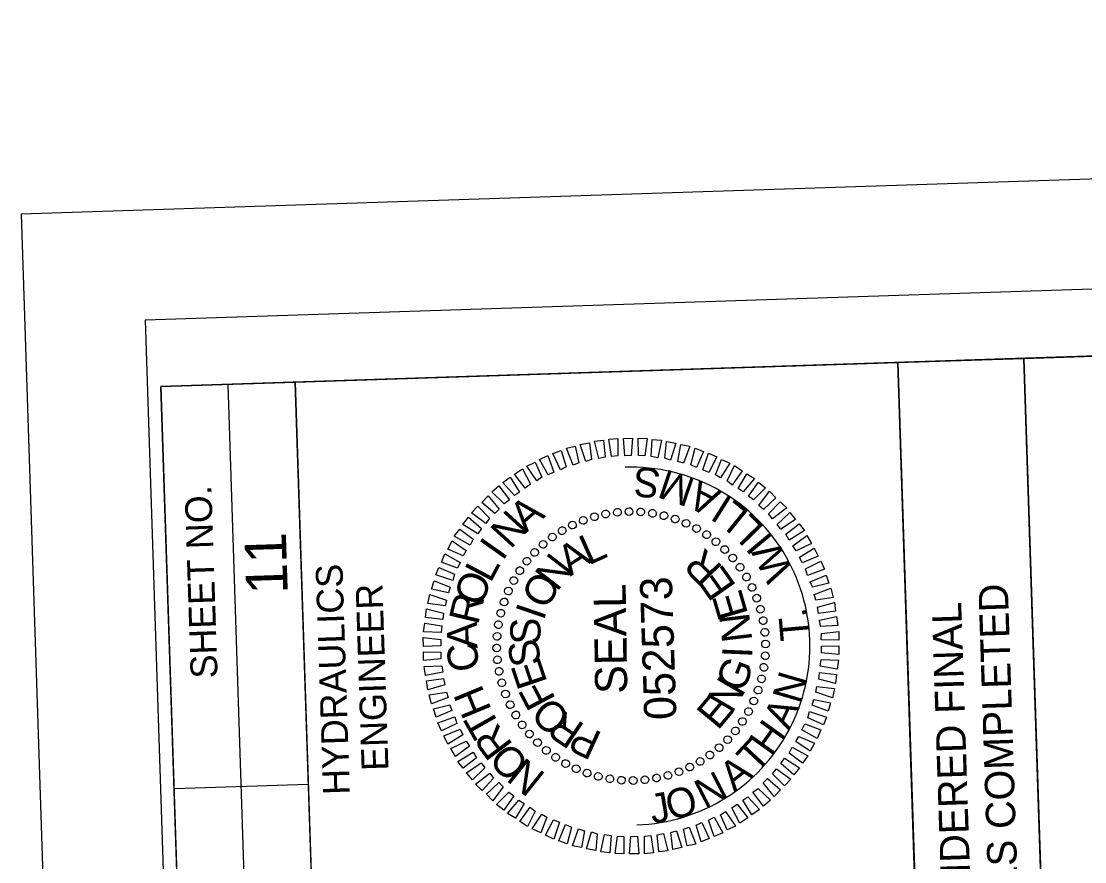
# Model space of a CAD drawing. Extents: x 1627314 to 1628469, y 762309 to 764253.
# Drawn here: x 1627314.2 to 1627512.6, y 763887.6 to 764044.4 of the extents above; entities that cross this region are included whole.
import ezdxf

# ---------------------------------------------------------------- set-up
doc = ezdxf.new("R2010")
doc.units = 0
for name, color, linetype in [('Old_Level_58', 7, 'Continuous'), ('Scratch_Level_0', 7, 'Continuous'), ('Sheet Data Field CELL', 7, 'Continuous'), ('Sheet Plot Border Inside CELL', 7, 'Continuous'), ('Sheet Plot Border Outside CELL', 7, 'Continuous'), ('Sheet Professional Seal CELL', 7, 'Continuous'), ('Sheet Profile CELL', 7, 'Continuous'), ('Sheet Profile Grid Major CELL', 7, 'Continuous'), ('Sheet Profile Grid Minor CELL', 7, 'Continuous'), ('Sheet Sticker Exception Certification CELL', 7, 'Continuous')]:
    doc.layers.add(name, color=color, linetype=linetype)

msp = doc.modelspace()

# ---------------------------------------------------------------- linework, layer by layer
at = {"layer": 'Old_Level_58'}
msp.add_lwpolyline([(1627507.79, 763781.61), (1627501.25, 763981.49), (1627565.16, 763983.58), (1627571.7, 763783.7)], close=True, dxfattribs=at)
at = {"layer": 'Scratch_Level_0'}
msp.add_arc((1627428, 763927.84), 33.36, 271.8735, 91.8735, dxfattribs=at)
at = {"layer": 'Sheet Plot Border Inside CELL'}
msp.add_lwpolyline([(1628446.34, 762357.53), (1628391.86, 764023.14), (1627337.33, 763988.65), (1627391.81, 762323.04)], close=True, dxfattribs=at)
at = {"layer": 'Sheet Plot Border Outside CELL'}
msp.add_lwpolyline([(1628469.21, 762345.27), (1628413.63, 764044.37), (1627314.22, 764008.4), (1627369.79, 762309.31)], close=True, dxfattribs=at)
at = {"layer": 'Sheet Professional Seal CELL'}
for p, q in [((1627421.1, 763951.98), (1627421.1, 763951.98)), ((1627423.29, 763952.45), (1627423.29, 763952.45)), ((1627425.43, 763952.82), (1627425.43, 763952.82)), ((1627427.62, 763952.94), (1627427.62, 763952.94)), ((1627429.83, 763952.86), (1627429.83, 763952.86)), ((1627431.99, 763952.58), (1627431.99, 763952.58)), ((1627434.1, 763952.2), (1627434.1, 763952.2)), ((1627436.22, 763951.57), (1627436.22, 763951.57)), ((1627417.05, 763950.44), (1627417.05, 763950.44)), ((1627419.02, 763951.31), (1627419.02, 763951.31)), ((1627438.25, 763950.74), (1627438.25, 763950.74)), ((1627440.23, 763949.8), (1627440.23, 763949.8)), ((1627413.27, 763948.17), (1627413.27, 763948.17)), ((1627415.13, 763949.38), (1627415.13, 763949.38)), ((1627442.07, 763948.61), (1627442.07, 763948.61)), ((1627411.56, 763946.86), (1627411.56, 763946.86)), ((1627443.87, 763947.32), (1627443.87, 763947.32)), ((1627445.47, 763945.87), (1627445.47, 763945.87)), ((1627408.52, 763943.71), (1627408.52, 763943.71)), ((1627409.96, 763945.31), (1627409.96, 763945.31)), ((1627447.02, 763944.27), (1627447.02, 763944.27)), ((1627407.22, 763941.92), (1627407.22, 763941.92)), ((1627448.33, 763942.56), (1627448.33, 763942.56)), ((1627406.03, 763940.08), (1627406.03, 763940.08)), ((1627449.54, 763940.7), (1627449.54, 763940.7)), ((1627405.1, 763938.1), (1627405.1, 763938.1)), ((1627450.6, 763938.78), (1627450.6, 763938.78)), ((1627404.26, 763936.07), (1627404.26, 763936.07)), ((1627451.46, 763936.81), (1627451.46, 763936.81)), ((1627403.63, 763933.95), (1627403.63, 763933.95)), ((1627452.13, 763934.73), (1627452.13, 763934.73)), ((1627403.25, 763931.83), (1627403.25, 763931.83)), ((1627452.6, 763932.55), (1627452.6, 763932.55)), ((1627402.97, 763929.67), (1627402.97, 763929.67)), ((1627452.98, 763930.41), (1627452.98, 763930.41)), ((1627428, 763927.84), (1627428, 763927.84)), ((1627453.1, 763928.21), (1627453.1, 763928.21)), ((1627402.89, 763927.47), (1627402.89, 763927.47)), ((1627453.02, 763926.01), (1627453.02, 763926.01)), ((1627403.02, 763925.27), (1627403.02, 763925.27)), ((1627452.74, 763923.85), (1627452.74, 763923.85)), ((1627403.39, 763923.13), (1627403.39, 763923.13)), ((1627452.36, 763921.73), (1627452.36, 763921.73)), ((1627403.86, 763920.95), (1627403.86, 763920.95)), ((1627404.53, 763918.87), (1627404.53, 763918.87)), ((1627451.73, 763919.61), (1627451.73, 763919.61)), ((1627405.39, 763916.89), (1627405.39, 763916.89)), ((1627450.89, 763917.58), (1627450.89, 763917.58)), ((1627406.45, 763914.98), (1627406.45, 763914.98)), ((1627448.77, 763913.76), (1627448.77, 763913.76)), ((1627449.96, 763915.6), (1627449.96, 763915.6)), ((1627407.67, 763913.12), (1627407.67, 763913.12)), ((1627447.47, 763911.97), (1627447.47, 763911.97)), ((1627408.97, 763911.41), (1627408.97, 763911.41)), ((1627410.53, 763909.81), (1627410.53, 763909.81)), ((1627446.03, 763910.37), (1627446.03, 763910.37)), ((1627412.12, 763908.36), (1627412.12, 763908.36)), ((1627444.43, 763908.82), (1627444.43, 763908.82)), ((1627413.92, 763907.07), (1627413.92, 763907.07)), ((1627415.76, 763905.88), (1627415.76, 763905.88)), ((1627440.86, 763906.3), (1627440.86, 763906.3)), ((1627442.72, 763907.51), (1627442.72, 763907.51)), ((1627417.74, 763904.94), (1627417.74, 763904.94)), ((1627419.77, 763904.11), (1627419.77, 763904.11)), ((1627436.97, 763904.37), (1627436.97, 763904.37)), ((1627438.94, 763905.23), (1627438.94, 763905.23)), ((1627421.89, 763903.48), (1627421.89, 763903.48)), ((1627424, 763903.09), (1627424, 763903.09)), ((1627426.16, 763902.82), (1627426.16, 763902.82)), ((1627428.37, 763902.74), (1627428.37, 763902.74)), ((1627430.56, 763902.86), (1627430.56, 763902.86)), ((1627432.7, 763903.23), (1627432.7, 763903.23)), ((1627434.89, 763903.7), (1627434.89, 763903.7))]:
    msp.add_line(p, q, dxfattribs=at)
for points in [[(1627419.57, 763962.28), (1627418.51, 763965.4), (1627420.2, 763965.75), (1627420.6, 763962.62)], [(1627421.95, 763962.81), (1627421.14, 763966.03), (1627422.84, 763966.24), (1627423.14, 763963.05)], [(1627424.34, 763963.19), (1627423.83, 763966.42), (1627425.53, 763966.58), (1627425.53, 763963.33)], [(1627426.84, 763963.32), (1627426.58, 763966.56), (1627428.28, 763966.62), (1627428.03, 763963.36)], [(1627429.34, 763963.35), (1627429.33, 763966.6), (1627430.98, 763966.56), (1627430.54, 763963.29)], [(1627431.74, 763963.18), (1627431.94, 763966.39), (1627433.64, 763966.24), (1627432.95, 763962.97)], [(1627434.3, 763962.86), (1627434.6, 763965.97), (1627436.31, 763965.68), (1627435.37, 763962.5)], [(1627436.72, 763962.29), (1627437.27, 763965.41), (1627438.93, 763965.12), (1627437.79, 763961.93)], [(1627412.49, 763959.75), (1627410.9, 763962.65), (1627412.48, 763963.35), (1627413.58, 763960.28)], [(1627414.81, 763960.72), (1627413.41, 763963.73), (1627414.95, 763964.33), (1627415.85, 763961.26)], [(1627417.19, 763961.6), (1627415.93, 763964.76), (1627417.57, 763965.12), (1627418.22, 763961.99)], [(1627439.15, 763961.62), (1627439.95, 763964.75), (1627441.52, 763964.15), (1627440.21, 763961.11)], [(1627441.38, 763960.69), (1627442.43, 763963.83), (1627444, 763963.13), (1627442.49, 763960.23)], [(1627410.38, 763958.68), (1627408.54, 763961.42), (1627410.07, 763962.12), (1627411.31, 763959.31)], [(1627443.71, 763959.77), (1627444.87, 763962.66), (1627446.44, 763961.96), (1627444.68, 763959.2)], [(1627445.9, 763958.64), (1627447.31, 763961.49), (1627448.74, 763960.53), (1627446.82, 763957.87)], [(1627408.22, 763957.31), (1627406.24, 763959.89), (1627407.7, 763960.89), (1627409.2, 763958.04)], [(1627447.95, 763957.21), (1627449.56, 763959.96), (1627451.04, 763959.06), (1627448.92, 763956.59)], [(1627404.32, 763954.38), (1627401.99, 763956.6), (1627403.31, 763957.7), (1627405.29, 763955.11)], [(1627406.22, 763955.94), (1627404.04, 763958.32), (1627405.45, 763959.32), (1627407.15, 763956.57)], [(1627449.89, 763955.77), (1627451.76, 763958.43), (1627453.09, 763957.37), (1627450.82, 763955.1)], [(1627402.57, 763952.57), (1627400.15, 763954.64), (1627401.31, 763955.88), (1627403.35, 763953.35)], [(1627451.85, 763954.08), (1627453.82, 763956.7), (1627455.01, 763955.49), (1627452.68, 763953.31)], [(1627400.88, 763950.71), (1627398.22, 763952.68), (1627399.38, 763953.92), (1627401.6, 763951.69)], [(1627453.65, 763952.49), (1627455.78, 763954.76), (1627457.02, 763953.6), (1627454.38, 763951.56)], [(1627399.4, 763948.76), (1627396.59, 763950.52), (1627397.64, 763951.86), (1627400.06, 763949.74)], [(1627455.27, 763950.54), (1627457.6, 763952.77), (1627458.69, 763951.45), (1627455.95, 763949.61)], [(1627397.96, 763946.67), (1627395.01, 763948.32), (1627396.02, 763949.65), (1627398.53, 763947.79)], [(1627456.83, 763948.69), (1627459.32, 763950.62), (1627460.31, 763949.36), (1627457.46, 763947.61)], [(1627396.68, 763944.67), (1627393.79, 763945.93), (1627394.59, 763947.46), (1627397.25, 763945.64)], [(1627458.15, 763946.53), (1627460.79, 763948.47), (1627461.64, 763946.95), (1627458.78, 763945.6)], [(1627459.42, 763944.42), (1627462.17, 763946.12), (1627462.92, 763944.59), (1627459.91, 763943.34)], [(1627395.6, 763942.34), (1627392.62, 763943.49), (1627393.26, 763945.06), (1627396.12, 763943.45)], [(1627460.54, 763942.26), (1627463.4, 763943.65), (1627464.05, 763942.17), (1627460.88, 763941.02)], [(1627394.73, 763940.06), (1627391.54, 763941.1), (1627392.1, 763942.52), (1627395.04, 763941.22)], [(1627393.9, 763937.78), (1627390.78, 763938.43), (1627391.23, 763939.99), (1627394.22, 763938.84)], [(1627461.42, 763939.84), (1627464.38, 763941.08), (1627464.88, 763939.55), (1627461.81, 763938.8)], [(1627462.15, 763937.46), (1627465.26, 763938.61), (1627465.67, 763936.92), (1627462.43, 763936.42)], [(1627393.33, 763935.36), (1627390.07, 763935.75), (1627390.41, 763937.46), (1627393.55, 763936.42)], [(1627462.78, 763935.08), (1627465.95, 763935.98), (1627466.15, 763934.34), (1627462.97, 763933.88)], [(1627392.86, 763932.79), (1627389.65, 763933.14), (1627389.85, 763934.79), (1627392.98, 763934)], [(1627392.54, 763930.38), (1627389.29, 763930.47), (1627389.53, 763932.13), (1627392.7, 763931.59)], [(1627463.16, 763932.69), (1627466.34, 763933.34), (1627466.59, 763931.65), (1627463.34, 763931.5)], [(1627463.49, 763930.2), (1627466.73, 763930.56), (1627466.73, 763928.91), (1627463.48, 763929)], [(1627392.48, 763927.88), (1627389.23, 763927.77), (1627389.22, 763929.42), (1627392.49, 763929.08)], [(1627463.52, 763927.8), (1627466.76, 763927.91), (1627466.77, 763926.26), (1627463.51, 763926.6)], [(1627392.5, 763925.48), (1627389.26, 763925.12), (1627389.26, 763926.77), (1627392.51, 763926.68)], [(1627392.84, 763922.99), (1627389.66, 763922.33), (1627389.4, 763924.02), (1627392.65, 763924.18)], [(1627463.45, 763925.3), (1627466.7, 763925.2), (1627466.46, 763923.54), (1627463.29, 763924.09)], [(1627393.21, 763920.6), (1627390.04, 763919.69), (1627389.84, 763921.34), (1627393.02, 763921.79)], [(1627463.13, 763922.88), (1627466.34, 763922.54), (1627466.14, 763920.88), (1627463.02, 763921.68)], [(1627462.66, 763920.32), (1627465.92, 763919.92), (1627465.58, 763918.21), (1627462.44, 763919.26)], [(1627393.84, 763918.22), (1627390.73, 763917.06), (1627390.32, 763918.75), (1627393.56, 763919.26)], [(1627462.09, 763917.9), (1627465.21, 763917.25), (1627464.76, 763915.68), (1627461.77, 763916.84)], [(1627394.57, 763915.84), (1627391.61, 763914.59), (1627391.11, 763916.13), (1627394.19, 763916.88)], [(1627395.45, 763913.42), (1627392.59, 763912.02), (1627391.95, 763913.5), (1627395.11, 763914.66)], [(1627461.26, 763915.62), (1627464.45, 763914.57), (1627463.89, 763913.15), (1627460.95, 763914.46)], [(1627396.57, 763911.25), (1627393.82, 763909.56), (1627393.07, 763911.09), (1627396.09, 763912.34)], [(1627460.39, 763913.34), (1627463.38, 763912.19), (1627462.73, 763910.61), (1627459.87, 763912.22)], [(1627397.84, 763909.14), (1627395.2, 763907.21), (1627394.35, 763908.73), (1627397.21, 763910.07)], [(1627459.31, 763911), (1627462.21, 763909.75), (1627461.4, 763908.22), (1627458.74, 763910.03)], [(1627399.16, 763906.98), (1627396.67, 763905.05), (1627395.68, 763906.32), (1627398.53, 763908.06)], [(1627458.03, 763909.01), (1627460.98, 763907.36), (1627459.98, 763906.02), (1627457.46, 763907.89)], [(1627400.72, 763905.13), (1627398.39, 763902.91), (1627397.3, 763904.22), (1627400.04, 763906.06)], [(1627456.6, 763906.91), (1627459.4, 763905.15), (1627458.35, 763903.82), (1627455.93, 763905.94)], [(1627402.34, 763903.19), (1627400.21, 763900.92), (1627398.97, 763902.08), (1627401.61, 763904.11)], [(1627455.11, 763904.96), (1627457.77, 763903), (1627456.61, 763901.76), (1627454.39, 763903.99)], [(1627404.14, 763901.59), (1627402.18, 763898.98), (1627400.99, 763900.19), (1627403.32, 763902.37)], [(1627453.42, 763903.11), (1627455.84, 763901.03), (1627454.68, 763899.8), (1627452.64, 763902.33)], [(1627406.1, 763899.91), (1627404.23, 763897.25), (1627402.9, 763898.3), (1627405.17, 763900.58)], [(1627451.68, 763901.3), (1627454, 763899.07), (1627452.68, 763897.98), (1627450.7, 763900.57)], [(1627408.05, 763898.47), (1627406.43, 763895.72), (1627404.95, 763896.62), (1627407.07, 763899.09)], [(1627447.77, 763898.37), (1627449.76, 763895.78), (1627448.29, 763894.78), (1627446.79, 763897.64)], [(1627449.78, 763899.74), (1627451.95, 763897.36), (1627450.54, 763896.36), (1627448.85, 763899.1)], [(1627410.09, 763897.04), (1627408.69, 763894.19), (1627407.25, 763895.14), (1627409.17, 763897.81)], [(1627412.28, 763895.91), (1627411.12, 763893.02), (1627409.55, 763893.72), (1627411.31, 763896.48)], [(1627443.5, 763895.93), (1627445.09, 763893.03), (1627443.51, 763892.33), (1627442.41, 763895.39)], [(1627445.61, 763897), (1627447.45, 763894.26), (1627445.93, 763893.56), (1627444.68, 763896.37)], [(1627414.61, 763894.98), (1627413.56, 763891.85), (1627411.99, 763892.55), (1627413.5, 763895.45)], [(1627416.84, 763894.06), (1627416.05, 763890.93), (1627414.48, 763891.53), (1627415.78, 763894.57)], [(1627438.81, 763894.07), (1627440.06, 763890.91), (1627438.42, 763890.56), (1627437.77, 763893.69)], [(1627441.18, 763894.95), (1627442.58, 763891.95), (1627441.05, 763891.35), (1627440.14, 763894.42)], [(1627419.27, 763893.38), (1627418.72, 763890.26), (1627417.06, 763890.56), (1627418.2, 763893.75)], [(1627421.69, 763892.81), (1627421.39, 763889.7), (1627419.68, 763890), (1627420.62, 763893.18)], [(1627424.25, 763892.5), (1627424.05, 763889.29), (1627422.35, 763889.43), (1627423.04, 763892.71)], [(1627426.66, 763892.33), (1627426.66, 763889.07), (1627425.01, 763889.12), (1627425.45, 763892.39)], [(1627429.16, 763892.36), (1627429.41, 763889.11), (1627427.71, 763889.06), (1627427.96, 763892.32)], [(1627431.65, 763892.49), (1627432.16, 763889.25), (1627430.46, 763889.1), (1627430.46, 763892.35)], [(1627434.04, 763892.87), (1627434.85, 763889.64), (1627433.15, 763889.44), (1627432.85, 763892.63)], [(1627436.43, 763893.4), (1627437.48, 763890.28), (1627435.79, 763889.92), (1627435.39, 763893.06)]]:
    msp.add_lwpolyline(points, close=True, dxfattribs=at)
for centre, major_axis in [((1627425.43, 763952.79), (-0.074, 0.716)), ((1627427.61, 763952.92), (-0.011, 0.72)), ((1627429.8, 763952.85), (0.052, 0.718)), ((1627419.06, 763951.27), (-0.257, 0.673)), ((1627421.14, 763951.96), (-0.197, 0.693)), ((1627423.26, 763952.47), (-0.136, 0.707)), ((1627431.97, 763952.6), (0.114, 0.711)), ((1627434.12, 763952.16), (0.176, 0.698)), ((1627436.21, 763951.53), (0.236, 0.68)), ((1627438.25, 763950.73), (0.294, 0.657)), ((1627415.13, 763949.36), (-0.369, 0.618)), ((1627417.05, 763950.4), (-0.314, 0.648)), ((1627440.2, 763949.75), (0.35, 0.629)), ((1627411.58, 763946.8), (-0.471, 0.544)), ((1627413.3, 763948.16), (-0.422, 0.583)), ((1627442.07, 763948.6), (0.404, 0.596)), ((1627443.82, 763947.29), (0.454, 0.559)), ((1627409.99, 763945.3), (-0.517, 0.501)), ((1627445.46, 763945.84), (0.501, 0.517)), ((1627408.54, 763943.66), (-0.559, 0.454)), ((1627446.96, 763944.25), (0.544, 0.471)), ((1627407.23, 763941.91), (-0.596, 0.404)), ((1627448.32, 763942.54), (0.583, 0.422)), ((1627449.52, 763940.71), (0.618, 0.369)), ((1627406.09, 763940.05), (-0.629, 0.35)), ((1627450.56, 763938.78), (0.648, 0.314)), ((1627405.11, 763938.09), (-0.657, 0.294)), ((1627451.43, 763936.77), (0.673, 0.257)), ((1627404.3, 763936.06), (-0.68, 0.236)), ((1627403.67, 763933.96), (-0.698, 0.176)), ((1627452.12, 763934.7), (0.693, 0.197)), ((1627403.23, 763931.82), (-0.711, 0.114)), ((1627452.63, 763932.57), (0.707, 0.136)), ((1627402.98, 763929.64), (-0.718, 0.052)), ((1627452.94, 763930.4), (0.716, 0.074)), ((1627402.92, 763927.46), (-0.72, -0.011)), ((1627453.07, 763928.22), (0.72, 0.011)), ((1627403.05, 763925.27), (-0.716, -0.074)), ((1627453.01, 763926.03), (0.718, -0.052)), ((1627403.37, 763923.11), (-0.707, -0.136)), ((1627452.76, 763923.86), (0.711, -0.114)), ((1627403.87, 763920.98), (-0.693, -0.197)), ((1627452.32, 763921.72), (0.698, -0.176)), ((1627404.56, 763918.9), (-0.673, -0.257)), ((1627451.69, 763919.62), (0.68, -0.236)), ((1627405.43, 763916.89), (-0.648, -0.314)), ((1627450.88, 763917.59), (0.657, -0.294)), ((1627406.47, 763914.97), (-0.618, -0.369)), ((1627449.9, 763915.63), (0.629, -0.35)), ((1627407.67, 763913.14), (-0.583, -0.422)), ((1627448.76, 763913.77), (0.596, -0.404)), ((1627409.03, 763911.43), (-0.544, -0.471)), ((1627447.45, 763912.01), (0.559, -0.454)), ((1627410.53, 763909.84), (-0.501, -0.517)), ((1627446, 763910.38), (0.517, -0.501)), ((1627412.17, 763908.38), (-0.454, -0.559)), ((1627413.93, 763907.08), (-0.404, -0.596)), ((1627442.69, 763907.52), (0.422, -0.583)), ((1627444.41, 763908.87), (0.471, -0.544)), ((1627415.79, 763905.93), (-0.35, -0.629)), ((1627438.94, 763905.27), (0.314, -0.648)), ((1627440.87, 763906.31), (0.369, -0.618)), ((1627417.74, 763904.95), (-0.294, -0.657)), ((1627419.78, 763904.14), (-0.236, -0.68)), ((1627421.87, 763903.52), (-0.176, -0.698)), ((1627424.02, 763903.08), (-0.114, -0.711)), ((1627432.73, 763903.21), (0.136, -0.707)), ((1627434.86, 763903.71), (0.197, -0.693)), ((1627436.93, 763904.4), (0.257, -0.673)), ((1627426.19, 763902.82), (-0.052, -0.718)), ((1627428.38, 763902.76), (0.011, -0.72)), ((1627430.56, 763902.89), (0.074, -0.716))]:
    msp.add_ellipse(centre, major_axis=major_axis, ratio=0.999708, dxfattribs=at)
at = {"layer": 'Sheet Profile CELL'}
for p, q in [((1627359.37, 763776.71), (1627352.83, 763976.65)), ((1627342.78, 763901.28), (1627367.77, 763902.1))]:
    msp.add_line(p, q, dxfattribs=at)
for points in [[(1627340.28, 763976.24), (1627389.32, 762477.04), (1628438.76, 762511.37), (1628389.72, 764010.57)], [(1627368.59, 763877.11), (1627365.32, 763977.06), (1627477.76, 763980.74), (1627481.03, 763880.79)], [(1627346.82, 763776.3), (1627340.28, 763976.24), (1627365.32, 763977.06), (1627371.86, 763777.12)]]:
    msp.add_lwpolyline(points, close=True, dxfattribs=at)
at = {"layer": 'Sheet Profile Grid Major CELL'}
msp.add_lwpolyline([(1627566.8, 763933.62), (1627841.65, 763942.61), (1627840.02, 763992.59), (1627490.2, 763981.14)], dxfattribs=at)
at = {"layer": 'Sheet Sticker Exception Certification CELL'}
for p, q in [((1627477.77, 763980.72), (1627501.26, 763981.49)), ((1627477.77, 763980.72), (1627501.26, 763981.49)), ((1627501.25, 763981.49), (1627507.79, 763781.56)), ((1627501.25, 763981.49), (1627507.79, 763781.56)), ((1627484.3, 763780.79), (1627477.76, 763980.72)), ((1627484.3, 763780.79), (1627477.76, 763980.72))]:
    msp.add_line(p, q, dxfattribs=at)

# ---------------------------------------------------------------- texts
at = {"layer": 'Old_Level_58'}
for s, rotation, p in [('S', 173.0617, (1627433.71, 763960.75)), ('M', 161.4413, (1627440.22, 763958.93)), ('A', 152.311, (1627445, 763956.6)), ('I', 147.846, (1627447.18, 763955.18)), ('L', 141.0913, (1627450.27, 763952.74)), ('L', 134.3366, (1627453.04, 763949.94)), ('I', 129.8716, (1627454.69, 763947.93)), ('W', 117.321, (1627458.41, 763941.65)), ('.', 102.2517, (1627460.96, 763933.26)), ('T', 95.0104, (1627461.38, 763929.07)), ('N', 73.7445, (1627459.55, 763916.87)), ('A', 64.6142, (1627457.41, 763912.01)), ('H', 54.4249, (1627454.15, 763907.05)), ('T', 47.1836, (1627451.32, 763903.92)), ('A', 38.0533, (1627447.23, 763900.52)), ('N', 27.1771, (1627441.73, 763897.38)), ('J', 9.715, (1627431.96, 763894.67)), ('O', 15.528, (1627435.3, 763895.24))]:
    msp.add_text(s, height=5.5, rotation=rotation, dxfattribs=at).set_placement(p)
at = {"layer": 'Sheet Data Field CELL'}
msp.add_text('11', height=7.75, rotation=91.8735, dxfattribs=at).set_placement((1627363.95, 763937.62))
at = {"layer": 'Sheet Professional Seal CELL'}
for s, height, rotation, p in [('A', 5.64, 40.4906, (1627408.35, 763948.81)), ('N', 5.64, 47.6924, (1627405.5, 763945.76)), ('I', 5.64, 54.8936, (1627404.02, 763943.56)), ('L', 5.64, 24.2743, (1627420.05, 763942.84)), ('A', 5.64, 33.6337, (1627416.67, 763940.77)), ('R', 5.64, 134.3549, (1627445.28, 763942.51)), ('N', 5.64, 52.3501, (1627414.16, 763937.84)), ('L', 5.64, 62.0943, (1627401.75, 763939.44)), ('E', 5.64, 124.9976, (1627447.74, 763939.04)), ('O', 5.64, 69.2946, (1627400.05, 763934.98)), ('O', 5.64, 61.707, (1627412.27, 763934.43)), ('SEAL', 5.998, 90.8735, (1627427.29, 763918.96)), ('E', 5.64, 106.2852, (1627449.86, 763933.81)), ('R', 5.64, 76.4946, (1627399.41, 763931.61)), ('I', 5.64, 71.0631, (1627411.64, 763932.41)), ('N', 5.64, 96.9299, (1627450.62, 763928.88)), ('A', 5.64, 90.8938, (1627399.34, 763927.4)), ('S', 5.64, 89.7739, (1627411.08, 763928.09)), ('C', 5.64, 98.0933, (1627399.77, 763923.46)), ('S', 5.64, 99.1291, (1627411.25, 763924.49)), ('I', 5.64, 87.5747, (1627450.58, 763925.53)), ('E', 5.64, 108.4845, (1627412.41, 763921.08)), ('G', 5.64, 68.8637, (1627448.9, 763918.92)), ('N', 5.64, 59.5074, (1627446.77, 763915.05)), ('H', 5.64, 112.4929, (1627402.02, 763915.93)), ('F', 5.64, 117.8405, (1627414.01, 763917.93)), ('E', 5.64, 50.1504, (1627444.17, 763911.96)), ('O', 5.64, 136.5547, (1627417.07, 763914.72)), ('R', 5.64, 145.9131, (1627419.57, 763913.06)), ('T', 5.64, 119.6932, (1627403.78, 763912.74)), ('R', 5.64, 126.894, (1627406.09, 763909.41)), ('P', 5.64, 155.2724, (1627422.83, 763911.56)), ('O', 5.64, 134.0952, (1627409.3, 763906.07)), ('N', 5.64, 141.297, (1627412.27, 763903.86))]:
    msp.add_text(s, height=height, rotation=rotation, dxfattribs=at).set_placement(p)
at = {"layer": 'Sheet Profile CELL'}
for s, p in [('SHEET NO.', (1627350.85, 763921.87)), ('HYDRAULICS', (1627375.53, 763900.16)), ('ENGINEER', (1627382.73, 763904.65))]:
    msp.add_text(s, height=5, rotation=91.8735, dxfattribs=at).set_placement(p)
at = {"layer": 'Sheet Profile Grid Minor CELL'}
msp.add_text('052573', height=5.998, rotation=91.8735, dxfattribs=at).set_placement((1627436.46, 763914.15))
at = {"layer": 'Sheet Sticker Exception Certification CELL'}
for s, p in [('UNLESS ALL SIGNATURES COMPLETED', (1627502.91, 763797.41)), ('UNLESS ALL SIGNATURES COMPLETED', (1627502.91, 763797.41)), ('DOCUMENT NOT CONSIDERED FINAL', (1627493.95, 763802.19)), ('DOCUMENT NOT CONSIDERED FINAL', (1627493.95, 763802.19))]:
    msp.add_text(s, height=5.5, rotation=91.8735, dxfattribs=at).set_placement(p)

doc.saveas('drawing.dxf')
